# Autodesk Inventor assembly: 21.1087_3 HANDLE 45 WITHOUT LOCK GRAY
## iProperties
Created: 2007-03
Part Number: 21.1087_3 HANDLE 45 WITHOUT LOCK GRAY
Document SubType Name: Assembly
Designer: Andy Moles
Translation Standard: STEP AP214IS
File Name: 1000-U618_ASM
Preprocessor: PRO/ENGINEER BY PARAMETRIC TECHNOLOGY CORPORATION, 2003200
Postprocessor: Build: 344b, Release: 11 SP2 - Date: Fri 08/18/2006
Sent Units: MILLIMETERS
Uncertainty: 0.016645587992409998
Author: Andy Moles
